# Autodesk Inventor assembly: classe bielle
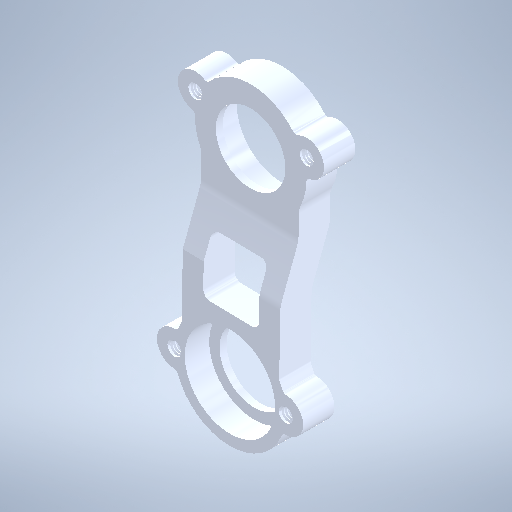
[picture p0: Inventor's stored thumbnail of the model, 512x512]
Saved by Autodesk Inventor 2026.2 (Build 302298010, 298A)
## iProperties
Created: 1601-01
Part Number: classe bielle
Document SubType Name: Assembly
Designer: mel
Part Number: Appareil_de_massage
Sending System: SOLIDWORKS 2023
Last Saved Date: 2025-04-02
Author: mel
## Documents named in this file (2)
- C:\Users\mel\Downloads\18256-itec-20250709t050547z-1-001 (1)\ITEC\Ressources\ITEC00_SW_Appareil_de_massage\S1Appareil_de_massage\S1Appareil_de_massage\classe bielle.iam
- C:\Users\mel\Downloads\18256-itec-20250709t050547z-1-001 (1)\ITEC\Ressources\ITEC00_SW_Appareil_de_massage\S1Appareil_de_massage\S1Appareil_de_massage\S1Bielle.ipt
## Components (1 placed, 1 different names)
1. Bielle-1
